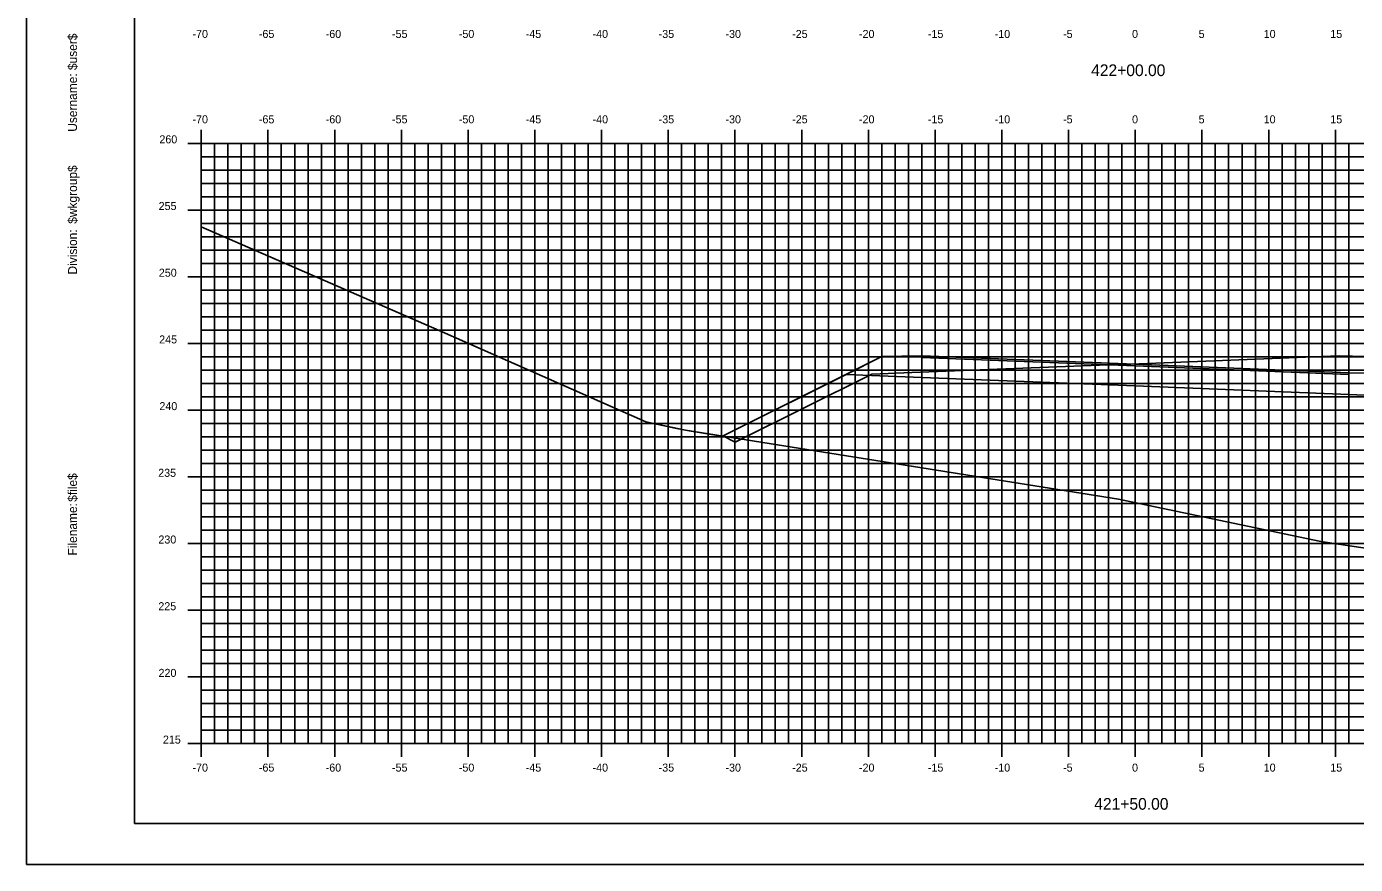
# Model space of a CAD drawing. Extents: x 1168600 to 1177589, y 610178 to 611246.
# Drawn here: x 1174215.3 to 1174314.9, y 610900.5 to 610963.3 of the extents above; entities that cross this region are included whole.
import ezdxf

# ---------------------------------------------------------------- set-up
doc = ezdxf.new("R2010")
doc.units = 0
for name, color, linetype in [('_Construction', 7, 'Continuous'), ('_Station Equation', 7, 'Continuous'), ('D_Roadway_Edge_TW', 7, 'Continuous'), ('D_Roadway_SubGrade', 7, 'Continuous'), ('D_Slope_Direction', 7, 'Continuous'), ('D_Text_Standard', 7, 'Continuous'), ('DIMENSIONS', 7, 'Continuous'), ('H_V ANNOTATION', 7, 'Continuous'), ('MAJOR', 7, 'Continuous'), ('MATCH LINES', 7, 'Continuous'), ('MINOR', 7, 'Continuous')]:
    doc.layers.add(name, color=color, linetype=linetype)

msp = doc.modelspace()

# ---------------------------------------------------------------- linework, layer by layer
at = {"layer": '_Construction'}
for p, q in [((1174223.367, 611008.596), (1174223.367, 610903.596)), ((1174223.367, 610903.596), (1174383.367, 610903.596))]:
    msp.add_line(p, q, dxfattribs=at)
msp.add_lwpolyline([(1174215.274, 610900.537), (1174385.274, 610900.537), (1174385.274, 611010.537), (1174215.274, 611010.537)], close=True, dxfattribs=at)
at = {"layer": '_Station Equation'}
for points in [[(1174228.367, 610948.347), (1174246.198, 610940.577), (1174261.693, 610933.725), (1174264.668, 610933.087), (1174297.116, 610927.92), (1174312.267, 610924.748), (1174318.764, 610923.769), (1174326.425, 610919.637), (1174328.67, 610919.022), (1174337.751, 610923.098), (1174368.367, 610938.545)], [(1174228.367, 610948.347), (1174246.203, 610940.574), (1174261.693, 610933.725), (1174263.896, 610933.253), (1174264.667, 610933.087), (1174264.922, 610933.046), (1174267.379, 610932.655), (1174267.395, 610932.652), (1174267.429, 610932.621), (1174267.436, 610932.636), (1174267.445, 610932.653), (1174267.452, 610932.657), (1174268.382, 610932.192), (1174268.528, 610932.265), (1174278.565, 610937.27), (1174278.61, 610937.293), (1174278.648, 610937.294), (1174281.613, 610937.41), (1174297.621, 610938.035), (1174297.626, 610938.035), (1174298.042, 610938.051), (1174313.63, 610938.661), (1174313.66, 610938.66), (1174316.63, 610938.598)]]:
    msp.add_lwpolyline(points, dxfattribs=at)
at = {"layer": 'D_Roadway_Edge_TW'}
msp.add_lwpolyline([(1174282.367, 610938.551), (1174282.367, 610938.676), (1174298.367, 610938.036), (1174314.367, 610937.396), (1174314.367, 610937.271), (1174298.367, 610937.911)], close=True, dxfattribs=at)
at = {"layer": 'D_Roadway_SubGrade'}
for points in [[(1174282.367, 610938.676), (1174279.367, 610938.616), (1174276.691, 610937.278), (1174282.367, 610937.051)], [(1174282.367, 610937.051), (1174282.367, 610938.551), (1174298.367, 610937.911), (1174314.367, 610937.271), (1174314.367, 610935.771), (1174298.367, 610936.411)], [(1174314.367, 610937.396), (1174317.367, 610937.336), (1174321.03, 610935.504), (1174314.367, 610935.771)]]:
    msp.add_lwpolyline(points, close=True, dxfattribs=at)
at = {"layer": 'D_Slope_Direction'}
for points in [[(1174279.367, 610938.616), (1174268.284, 610933.074)], [(1174268.284, 610933.074), (1174267.429, 610932.647)]]:
    msp.add_lwpolyline(points, dxfattribs=at)
at = {"layer": 'D_Text_Standard'}
msp.add_lwpolyline([(1174267.429, 610932.647), (1174268.284, 610933.074), (1174276.691, 610937.278), (1174279.367, 610938.616), (1174282.367, 610938.676), (1174298.367, 610938.036), (1174314.367, 610937.396), (1174317.367, 610937.336), (1174321.03, 610935.504), (1174328.45, 610931.794), (1174341.778, 610925.13)], dxfattribs=at)
at = {"layer": 'DIMENSIONS'}
msp.add_lwpolyline([(1174282.367, 610938.551), (1174282.367, 610938.551), (1174298.367, 610937.911), (1174314.367, 610937.271), (1174314.367, 610937.271), (1174298.367, 610937.911)], close=True, dxfattribs=at)
for points in [[(1174282.367, 610938.551), (1174282.367, 610938.551)], [(1174282.367, 610938.551), (1174282.367, 610938.551)], [(1174314.367, 610937.271), (1174314.367, 610937.271)], [(1174314.367, 610937.271), (1174314.367, 610937.271)]]:
    msp.add_lwpolyline(points, dxfattribs=at)
at = {"layer": 'MAJOR'}
for p, q in [((1174228.367, 610955.598), (1174228.367, 610954.596)), ((1174233.367, 610955.598), (1174233.367, 610954.596)), ((1174238.367, 610955.598), (1174238.367, 610954.596)), ((1174243.367, 610955.598), (1174243.367, 610954.596)), ((1174248.367, 610955.598), (1174248.367, 610954.596)), ((1174253.367, 610955.598), (1174253.367, 610954.596)), ((1174258.367, 610955.598), (1174258.367, 610954.596)), ((1174263.367, 610955.598), (1174263.367, 610954.596)), ((1174268.367, 610955.598), (1174268.367, 610954.596)), ((1174273.367, 610955.598), (1174273.367, 610954.596)), ((1174278.367, 610955.598), (1174278.367, 610954.596)), ((1174283.367, 610955.598), (1174283.367, 610954.596)), ((1174288.367, 610955.598), (1174288.367, 610954.596)), ((1174293.367, 610955.598), (1174293.367, 610954.596)), ((1174298.367, 610955.598), (1174298.367, 610954.596)), ((1174303.367, 610955.598), (1174303.367, 610954.596)), ((1174308.367, 610955.598), (1174308.367, 610954.596)), ((1174313.367, 610955.598), (1174313.367, 610954.596)), ((1174227.365, 610954.596), (1174228.367, 610954.596)), ((1174228.367, 610954.596), (1174368.367, 610954.596)), ((1174228.367, 610909.596), (1174228.367, 610954.596)), ((1174228.367, 610909.596), (1174228.367, 610954.596)), ((1174228.367, 610954.596), (1174368.367, 610954.596)), ((1174233.367, 610909.596), (1174233.367, 610954.596)), ((1174238.367, 610909.596), (1174238.367, 610954.596)), ((1174243.367, 610909.596), (1174243.367, 610954.596)), ((1174248.367, 610909.596), (1174248.367, 610954.596)), ((1174253.367, 610909.596), (1174253.367, 610954.596)), ((1174258.367, 610909.596), (1174258.367, 610954.596)), ((1174263.367, 610909.596), (1174263.367, 610954.596)), ((1174268.367, 610909.596), (1174268.367, 610954.596)), ((1174273.367, 610909.596), (1174273.367, 610954.596)), ((1174278.367, 610909.596), (1174278.367, 610954.596)), ((1174283.367, 610909.596), (1174283.367, 610954.596)), ((1174288.367, 610909.596), (1174288.367, 610954.596)), ((1174293.367, 610909.596), (1174293.367, 610954.596)), ((1174298.367, 610909.596), (1174298.367, 610954.596)), ((1174303.367, 610909.596), (1174303.367, 610954.596)), ((1174308.367, 610909.596), (1174308.367, 610954.596)), ((1174313.367, 610909.596), (1174313.367, 610954.596)), ((1174227.365, 610949.596), (1174228.367, 610949.596)), ((1174228.367, 610949.596), (1174368.367, 610949.596)), ((1174227.365, 610944.596), (1174228.367, 610944.596)), ((1174228.367, 610944.596), (1174368.367, 610944.596)), ((1174227.365, 610939.596), (1174228.367, 610939.596)), ((1174228.367, 610939.596), (1174368.367, 610939.596)), ((1174227.365, 610934.596), (1174228.367, 610934.596)), ((1174228.367, 610934.596), (1174368.367, 610934.596)), ((1174227.365, 610929.596), (1174228.367, 610929.596)), ((1174228.367, 610929.596), (1174368.367, 610929.596)), ((1174227.365, 610924.596), (1174228.367, 610924.596)), ((1174228.367, 610924.596), (1174368.367, 610924.596)), ((1174227.365, 610919.596), (1174228.367, 610919.596)), ((1174228.367, 610919.596), (1174368.367, 610919.596)), ((1174227.365, 610914.596), (1174228.367, 610914.596)), ((1174228.367, 610914.596), (1174368.367, 610914.596)), ((1174227.365, 610909.596), (1174228.367, 610909.596)), ((1174228.367, 610909.596), (1174368.367, 610909.596)), ((1174228.367, 610909.596), (1174368.367, 610909.596)), ((1174228.367, 610908.594), (1174228.367, 610909.596)), ((1174233.367, 610908.594), (1174233.367, 610909.596)), ((1174238.367, 610908.594), (1174238.367, 610909.596)), ((1174243.367, 610908.594), (1174243.367, 610909.596)), ((1174248.367, 610908.594), (1174248.367, 610909.596)), ((1174253.367, 610908.594), (1174253.367, 610909.596)), ((1174258.367, 610908.594), (1174258.367, 610909.596)), ((1174263.367, 610908.594), (1174263.367, 610909.596)), ((1174268.367, 610908.594), (1174268.367, 610909.596)), ((1174273.367, 610908.594), (1174273.367, 610909.596)), ((1174278.367, 610908.594), (1174278.367, 610909.596)), ((1174283.367, 610908.594), (1174283.367, 610909.596)), ((1174288.367, 610908.594), (1174288.367, 610909.596)), ((1174293.367, 610908.594), (1174293.367, 610909.596)), ((1174298.367, 610908.594), (1174298.367, 610909.596)), ((1174303.367, 610908.594), (1174303.367, 610909.596)), ((1174308.367, 610908.594), (1174308.367, 610909.596)), ((1174313.367, 610908.594), (1174313.367, 610909.596))]:
    msp.add_line(p, q, dxfattribs=at)
at = {"layer": 'MATCH LINES'}
for points in [[(1174282.367, 610938.676), (1174282.367, 610938.551)], [(1174314.367, 610937.396), (1174314.367, 610937.271)]]:
    msp.add_lwpolyline(points, dxfattribs=at)
at = {"layer": 'MINOR'}
for p, q in [((1174229.367, 610909.596), (1174229.367, 610954.596)), ((1174230.367, 610909.596), (1174230.367, 610954.596)), ((1174231.367, 610909.596), (1174231.367, 610954.596)), ((1174232.367, 610909.596), (1174232.367, 610954.596)), ((1174234.367, 610909.596), (1174234.367, 610954.596)), ((1174235.367, 610909.596), (1174235.367, 610954.596)), ((1174236.367, 610909.596), (1174236.367, 610954.596)), ((1174237.367, 610909.596), (1174237.367, 610954.596)), ((1174239.367, 610909.596), (1174239.367, 610954.596)), ((1174240.367, 610909.596), (1174240.367, 610954.596)), ((1174241.367, 610909.596), (1174241.367, 610954.596)), ((1174242.367, 610909.596), (1174242.367, 610954.596)), ((1174244.367, 610909.596), (1174244.367, 610954.596)), ((1174245.367, 610909.596), (1174245.367, 610954.596)), ((1174246.367, 610909.596), (1174246.367, 610954.596)), ((1174247.367, 610909.596), (1174247.367, 610954.596)), ((1174249.367, 610909.596), (1174249.367, 610954.596)), ((1174250.367, 610909.596), (1174250.367, 610954.596)), ((1174251.367, 610909.596), (1174251.367, 610954.596)), ((1174252.367, 610909.596), (1174252.367, 610954.596)), ((1174254.367, 610909.596), (1174254.367, 610954.596)), ((1174255.367, 610909.596), (1174255.367, 610954.596)), ((1174256.367, 610909.596), (1174256.367, 610954.596)), ((1174257.367, 610909.596), (1174257.367, 610954.596)), ((1174259.367, 610909.596), (1174259.367, 610954.596)), ((1174260.367, 610909.596), (1174260.367, 610954.596)), ((1174261.367, 610909.596), (1174261.367, 610954.596)), ((1174262.367, 610909.596), (1174262.367, 610954.596)), ((1174264.367, 610909.596), (1174264.367, 610954.596)), ((1174265.367, 610909.596), (1174265.367, 610954.596)), ((1174266.367, 610909.596), (1174266.367, 610954.596)), ((1174267.367, 610909.596), (1174267.367, 610954.596)), ((1174269.367, 610909.596), (1174269.367, 610954.596)), ((1174270.367, 610909.596), (1174270.367, 610954.596)), ((1174271.367, 610909.596), (1174271.367, 610954.596)), ((1174272.367, 610909.596), (1174272.367, 610954.596)), ((1174274.367, 610909.596), (1174274.367, 610954.596)), ((1174275.367, 610909.596), (1174275.367, 610954.596)), ((1174276.367, 610909.596), (1174276.367, 610954.596)), ((1174277.367, 610909.596), (1174277.367, 610954.596)), ((1174279.367, 610909.596), (1174279.367, 610954.596)), ((1174280.367, 610909.596), (1174280.367, 610954.596)), ((1174281.367, 610909.596), (1174281.367, 610954.596)), ((1174282.367, 610909.596), (1174282.367, 610954.596)), ((1174284.367, 610909.596), (1174284.367, 610954.596)), ((1174285.367, 610909.596), (1174285.367, 610954.596)), ((1174286.367, 610909.596), (1174286.367, 610954.596)), ((1174287.367, 610909.596), (1174287.367, 610954.596)), ((1174289.367, 610909.596), (1174289.367, 610954.596)), ((1174290.367, 610909.596), (1174290.367, 610954.596)), ((1174291.367, 610909.596), (1174291.367, 610954.596)), ((1174292.367, 610909.596), (1174292.367, 610954.596)), ((1174294.367, 610909.596), (1174294.367, 610954.596)), ((1174295.367, 610909.596), (1174295.367, 610954.596)), ((1174296.367, 610909.596), (1174296.367, 610954.596)), ((1174297.367, 610909.596), (1174297.367, 610954.596)), ((1174299.367, 610909.596), (1174299.367, 610954.596)), ((1174300.367, 610909.596), (1174300.367, 610954.596)), ((1174301.367, 610909.596), (1174301.367, 610954.596)), ((1174302.367, 610909.596), (1174302.367, 610954.596)), ((1174304.367, 610909.596), (1174304.367, 610954.596)), ((1174305.367, 610909.596), (1174305.367, 610954.596)), ((1174306.367, 610909.596), (1174306.367, 610954.596)), ((1174307.367, 610909.596), (1174307.367, 610954.596)), ((1174309.367, 610909.596), (1174309.367, 610954.596)), ((1174310.367, 610909.596), (1174310.367, 610954.596)), ((1174311.367, 610909.596), (1174311.367, 610954.596)), ((1174312.367, 610909.596), (1174312.367, 610954.596)), ((1174314.367, 610909.596), (1174314.367, 610954.596)), ((1174228.367, 610953.596), (1174368.367, 610953.596)), ((1174228.367, 610953.596), (1174229.369, 610953.596)), ((1174228.367, 610952.596), (1174368.367, 610952.596)), ((1174228.367, 610952.596), (1174229.369, 610952.596)), ((1174228.367, 610951.596), (1174368.367, 610951.596)), ((1174228.367, 610951.596), (1174229.369, 610951.596)), ((1174228.367, 610950.596), (1174368.367, 610950.596)), ((1174228.367, 610950.596), (1174229.369, 610950.596)), ((1174228.367, 610948.596), (1174368.367, 610948.596)), ((1174228.367, 610948.596), (1174229.369, 610948.596)), ((1174228.367, 610947.596), (1174368.367, 610947.596)), ((1174228.367, 610947.596), (1174229.369, 610947.596)), ((1174228.367, 610946.596), (1174368.367, 610946.596)), ((1174228.367, 610946.596), (1174229.369, 610946.596)), ((1174228.367, 610945.596), (1174368.367, 610945.596)), ((1174228.367, 610945.596), (1174229.369, 610945.596)), ((1174228.367, 610943.596), (1174368.367, 610943.596)), ((1174228.367, 610943.596), (1174229.369, 610943.596)), ((1174228.367, 610942.596), (1174368.367, 610942.596)), ((1174228.367, 610942.596), (1174229.369, 610942.596)), ((1174228.367, 610941.596), (1174368.367, 610941.596)), ((1174228.367, 610941.596), (1174229.369, 610941.596)), ((1174228.367, 610940.596), (1174368.367, 610940.596)), ((1174228.367, 610940.596), (1174229.369, 610940.596)), ((1174228.367, 610938.596), (1174368.367, 610938.596)), ((1174228.367, 610938.596), (1174229.369, 610938.596)), ((1174228.367, 610937.596), (1174368.367, 610937.596)), ((1174228.367, 610937.596), (1174229.369, 610937.596)), ((1174228.367, 610936.596), (1174368.367, 610936.596)), ((1174228.367, 610936.596), (1174229.369, 610936.596)), ((1174228.367, 610935.596), (1174368.367, 610935.596)), ((1174228.367, 610935.596), (1174229.369, 610935.596)), ((1174228.367, 610933.596), (1174368.367, 610933.596)), ((1174228.367, 610933.596), (1174229.369, 610933.596)), ((1174228.367, 610932.596), (1174368.367, 610932.596)), ((1174228.367, 610932.596), (1174229.369, 610932.596)), ((1174228.367, 610931.596), (1174368.367, 610931.596)), ((1174228.367, 610931.596), (1174229.369, 610931.596)), ((1174228.367, 610930.596), (1174368.367, 610930.596)), ((1174228.367, 610930.596), (1174229.369, 610930.596)), ((1174228.367, 610928.596), (1174368.367, 610928.596)), ((1174228.367, 610928.596), (1174229.369, 610928.596)), ((1174228.367, 610927.596), (1174368.367, 610927.596)), ((1174228.367, 610927.596), (1174229.369, 610927.596)), ((1174228.367, 610926.596), (1174368.367, 610926.596)), ((1174228.367, 610926.596), (1174229.369, 610926.596)), ((1174228.367, 610925.596), (1174368.367, 610925.596)), ((1174228.367, 610925.596), (1174229.369, 610925.596)), ((1174228.367, 610923.596), (1174368.367, 610923.596)), ((1174228.367, 610923.596), (1174229.369, 610923.596)), ((1174228.367, 610922.596), (1174368.367, 610922.596)), ((1174228.367, 610922.596), (1174229.369, 610922.596)), ((1174228.367, 610921.596), (1174368.367, 610921.596)), ((1174228.367, 610921.596), (1174229.369, 610921.596)), ((1174228.367, 610920.596), (1174368.367, 610920.596)), ((1174228.367, 610920.596), (1174229.369, 610920.596)), ((1174228.367, 610918.596), (1174368.367, 610918.596)), ((1174228.367, 610918.596), (1174229.369, 610918.596)), ((1174228.367, 610917.596), (1174368.367, 610917.596)), ((1174228.367, 610917.596), (1174229.369, 610917.596)), ((1174228.367, 610916.596), (1174368.367, 610916.596)), ((1174228.367, 610916.596), (1174229.369, 610916.596)), ((1174228.367, 610915.596), (1174368.367, 610915.596)), ((1174228.367, 610915.596), (1174229.369, 610915.596)), ((1174228.367, 610913.596), (1174368.367, 610913.596)), ((1174228.367, 610913.596), (1174229.369, 610913.596)), ((1174228.367, 610912.596), (1174368.367, 610912.596)), ((1174228.367, 610912.596), (1174229.369, 610912.596)), ((1174228.367, 610911.596), (1174368.367, 610911.596)), ((1174228.367, 610911.596), (1174229.369, 610911.596)), ((1174228.367, 610910.596), (1174368.367, 610910.596)), ((1174228.367, 610910.596), (1174229.369, 610910.596))]:
    msp.add_line(p, q, dxfattribs=at)

# ---------------------------------------------------------------- texts
at = {"layer": '_Construction'}
for s, p in [('$user$', (1174219.052, 610960.088)), ('Username:', (1174219.052, 610955.464)), ('$wkgroup$', (1174219.052, 610948.566)), ('Division:', (1174219.052, 610944.762)), ('$file$', (1174219.052, 610927.722)), ('Filename:', (1174219.052, 610923.695))]:
    msp.add_text(s, height=0.6696, rotation=90, dxfattribs=at).set_placement(p)
at = {"layer": 'H_V ANNOTATION'}
for s, height, p in [('-70', 0.6, (1174227.709, 610962.496)), ('-65', 0.6, (1174232.685, 610962.496)), ('-60', 0.6, (1174237.693, 610962.496)), ('-55', 0.6, (1174242.663, 610962.496)), ('-50', 0.6, (1174247.671, 610962.496)), ('-45', 0.6, (1174252.685, 610962.496)), ('-40', 0.6, (1174257.693, 610962.496)), ('-35', 0.6, (1174262.647, 610962.496)), ('-30', 0.6, (1174267.655, 610962.496)), ('-25', 0.6, (1174272.653, 610962.496)), ('-20', 0.6, (1174277.661, 610962.496)), ('-15', 0.6, (1174282.824, 610962.496)), ('-10', 0.6, (1174287.832, 610962.496)), ('-5', 0.6, (1174292.958, 610962.496)), ('0', 0.6, (1174298.126, 610962.496)), ('5', 0.6, (1174303.118, 610962.496)), ('10', 0.6, (1174307.992, 610962.496)), ('15', 0.6, (1174312.984, 610962.496)), ('422+00.00', 0.875, (1174295.059, 610959.639)), ('-70', 0.6, (1174227.709, 610956.096)), ('-65', 0.6, (1174232.685, 610956.096)), ('-60', 0.6, (1174237.693, 610956.096)), ('-55', 0.6, (1174242.663, 610956.096)), ('-50', 0.6, (1174247.671, 610956.096)), ('-45', 0.6, (1174252.685, 610956.096)), ('-40', 0.6, (1174257.693, 610956.096)), ('-35', 0.6, (1174262.647, 610956.096)), ('-30', 0.6, (1174267.655, 610956.096)), ('-25', 0.6, (1174272.653, 610956.096)), ('-20', 0.6, (1174277.661, 610956.096)), ('-15', 0.6, (1174282.824, 610956.096)), ('-10', 0.6, (1174287.832, 610956.096)), ('-5', 0.6, (1174292.958, 610956.096)), ('0', 0.6, (1174298.126, 610956.096)), ('5', 0.6, (1174303.118, 610956.096)), ('10', 0.6, (1174307.992, 610956.096)), ('15', 0.6, (1174312.984, 610956.096)), ('260', 0.6, (1174225.229, 610954.596)), ('255', 0.6, (1174225.17, 610949.596)), ('250', 0.6, (1174225.186, 610944.596)), ('245', 0.6, (1174225.213, 610939.596)), ('240', 0.6, (1174225.229, 610934.596)), ('235', 0.6, (1174225.138, 610929.596)), ('230', 0.6, (1174225.154, 610924.596)), ('225', 0.6, (1174225.149, 610919.596)), ('220', 0.6, (1174225.165, 610914.596)), ('215', 0.6, (1174225.492, 610909.596)), ('-70', 0.6, (1174227.709, 610907.496)), ('-65', 0.6, (1174232.685, 610907.496)), ('-60', 0.6, (1174237.693, 610907.496)), ('-55', 0.6, (1174242.663, 610907.496)), ('-50', 0.6, (1174247.671, 610907.496)), ('-45', 0.6, (1174252.685, 610907.496)), ('-40', 0.6, (1174257.693, 610907.496)), ('-35', 0.6, (1174262.647, 610907.496)), ('-30', 0.6, (1174267.655, 610907.496)), ('-25', 0.6, (1174272.653, 610907.496)), ('-20', 0.6, (1174277.661, 610907.496)), ('-15', 0.6, (1174282.824, 610907.496)), ('-10', 0.6, (1174287.832, 610907.496)), ('-5', 0.6, (1174292.958, 610907.496)), ('0', 0.6, (1174298.126, 610907.496)), ('5', 0.6, (1174303.118, 610907.496)), ('10', 0.6, (1174307.992, 610907.496)), ('15', 0.6, (1174312.984, 610907.496)), ('421+50.00', 0.875, (1174295.293, 610904.639))]:
    msp.add_text(s, height=height, dxfattribs=at).set_placement(p)

doc.saveas('drawing.dxf')
